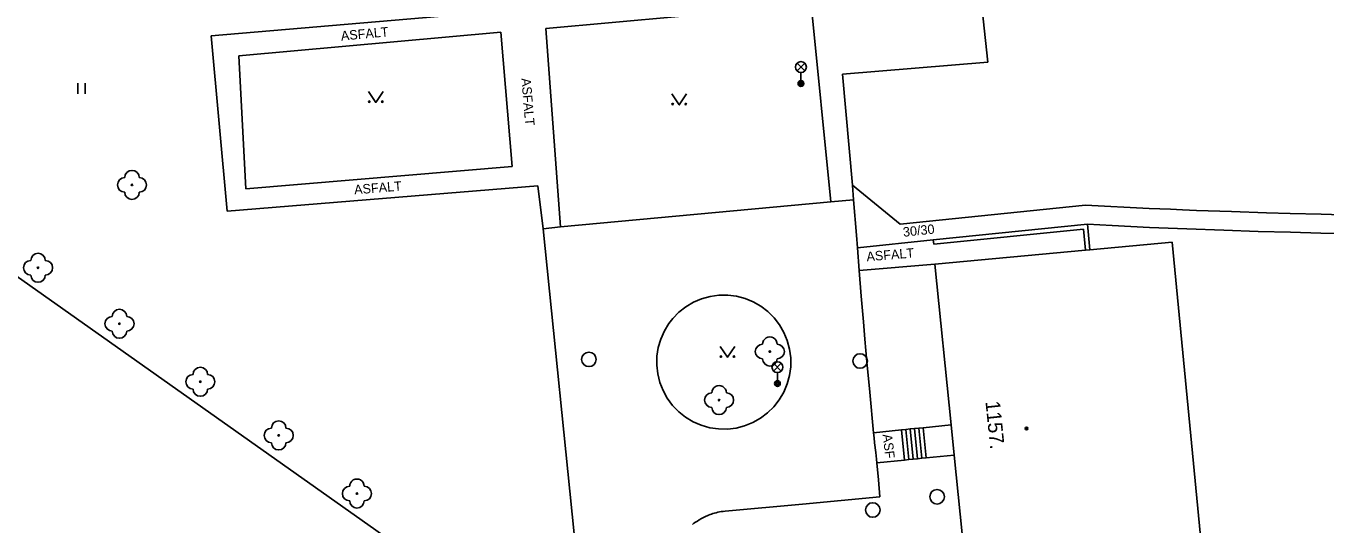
# Model space of a CAD drawing. Extents: x -539515 to -538098, y -1182060 to -1180157.
# Drawn here: x -538716.8 to -538627.4, y -1181091.3 to -1181057.1 of the extents above; entities that cross this region are included whole.
import ezdxf

# ---------------------------------------------------------------- set-up
doc = ezdxf.new("R2010")
doc.units = 0
for name, color, linetype in [('Vrstva 10', 7, 'Continuous'), ('Vrstva 11', 7, 'Continuous'), ('Vrstva 22', 7, 'Continuous'), ('Vrstva 27', 7, 'Continuous'), ('Vrstva 33', 7, 'Continuous'), ('Vrstva 36', 7, 'Continuous'), ('Vrstva 39', 7, 'Continuous'), ('Vrstva 40', 7, 'Continuous'), ('Vrstva 47', 7, 'Continuous'), ('Vrstva 5', 7, 'Continuous'), ('Vrstva 7', 7, 'Continuous')]:
    doc.layers.add(name, color=color, linetype=linetype)

msp = doc.modelspace()

# ---------------------------------------------------------------- linework, layer by layer
at = {"layer": 'Vrstva 10'}
for p, q in [((-538734.22, -1181062.4), (-538683.56, -1181098.18)), ((-538659.85, -1181069.02), (-538661.42, -1181069.16)), ((-538659.66, -1181071.445), (-538659.85, -1181069.02)), ((-538661.42, -1181069.16), (-538680, -1181070.87)), ((-538680, -1181070.87), (-538681.19, -1181071.01)), ((-538681.19, -1181071.01), (-538678.23, -1181100.27)), ((-538658.04, -1181089.45), (-538663.365, -1181089.94)), ((-538663.365, -1181089.94), (-538668.69, -1181090.43))]:
    msp.add_line(p, q, dxfattribs=at)
for points in [[(-538658.937, -1181080.161), (-538659.077, -1181078.589), (-538659.179, -1181077.409), (-538659.328, -1181075.64), (-538659.47, -1181073.87), (-538659.591, -1181072.326), (-538659.66, -1181071.445)], [(-538664.946, -1181077.612), (-538665.316, -1181077.131), (-538665.747, -1181076.702), (-538666.229, -1181076.334), (-538666.756, -1181076.033), (-538667.318, -1181075.803), (-538667.9, -1181075.65), (-538668.508, -1181075.573), (-538669.115, -1181075.578), (-538669.717, -1181075.662), (-538670.302, -1181075.824), (-538670.86, -1181076.062), (-538671.383, -1181076.371), (-538671.861, -1181076.746), (-538672.285, -1181077.18), (-538672.547, -1181077.517)], [(-538672.547, -1181077.517), (-538672.864, -1181078.035), (-538673.11, -1181078.59), (-538673.281, -1181079.173), (-538673.374, -1181079.773), (-538673.388, -1181080.38), (-538673.322, -1181080.983), (-538673.177, -1181081.573), (-538672.955, -1181082.138), (-538672.662, -1181082.67), (-538672.301, -1181083.158), (-538671.879, -1181083.595), (-538671.404, -1181083.972), (-538670.883, -1181084.284), (-538670.325, -1181084.525), (-538669.741, -1181084.69), (-538669.14, -1181084.777)], [(-538664.642, -1181078.138), (-538664.946, -1181077.612)], [(-538669.14, -1181084.777), (-538668.533, -1181084.785), (-538667.93, -1181084.713), (-538667.342, -1181084.562), (-538666.779, -1181084.335), (-538666.25, -1181084.037), (-538665.765, -1181083.671), (-538665.333, -1181083.245), (-538664.96, -1181082.766), (-538664.653, -1181082.242), (-538664.418, -1181081.682), (-538664.258, -1181081.096), (-538664.177, -1181080.495), (-538664.175, -1181079.887), (-538664.253, -1181079.285), (-538664.41, -1181078.699), (-538664.642, -1181078.138)], [(-538658.04, -1181089.45), (-538658.145, -1181088.28), (-538658.25, -1181087.11), (-538658.275, -1181086.852), (-538658.325, -1181086.401), (-538658.406, -1181085.726), (-538658.445, -1181085.388), (-538658.48, -1181085.05), (-538658.744, -1181082.256), (-538658.937, -1181080.161)], [(-538668.69, -1181090.43), (-538668.824, -1181090.445), (-538668.952, -1181090.463), (-538669.076, -1181090.486), (-538669.195, -1181090.511), (-538669.31, -1181090.539), (-538669.42, -1181090.569), (-538669.526, -1181090.601), (-538669.627, -1181090.635), (-538669.725, -1181090.671), (-538669.82, -1181090.708), (-538669.91, -1181090.745), (-538669.997, -1181090.784), (-538670.164, -1181090.864), (-538670.318, -1181090.945), (-538670.461, -1181091.026), (-538670.593, -1181091.108), (-538670.714, -1181091.187), (-538670.827, -1181091.266), (-538670.931, -1181091.342)]]:
    msp.add_lwpolyline(points, dxfattribs=at)
at = {"layer": 'Vrstva 11'}
for p, q in [((-538651.65, -1181049.65), (-538650.63, -1181059.54)), ((-538704.02, -1181057.74), (-538672.8, -1181055.06)), ((-538662.76, -1181055.59), (-538681.02, -1181057.24)), ((-538661.42, -1181069.16), (-538662.76, -1181055.59)), ((-538684.1, -1181057.49), (-538702.12, -1181059.12)), ((-538683.33, -1181066.73), (-538684.1, -1181057.49)), ((-538681.02, -1181057.24), (-538680, -1181070.87)), ((-538702.92, -1181069.8), (-538704.02, -1181057.74)), ((-538702.12, -1181059.12), (-538701.65, -1181068.25)), ((-538650.63, -1181059.54), (-538660.62, -1181060.37)), ((-538660.62, -1181060.37), (-538659.93, -1181068)), ((-538701.65, -1181068.25), (-538683.33, -1181066.73)), ((-538681.56, -1181068.05), (-538702.92, -1181069.8)), ((-538681.19, -1181071.01), (-538681.56, -1181068.05)), ((-538659.93, -1181068), (-538659.85, -1181069.02)), ((-538656.64, -1181070.68), (-538659.93, -1181068)), ((-538643.901, -1181069.386), (-538656.64, -1181070.68)), ((-538639.525, -1181069.601), (-538643.901, -1181069.386)), ((-538654.37, -1181071.77), (-538659.591, -1181072.326)), ((-538654.26, -1181073.44), (-538659.47, -1181073.87)), ((-538656.56, -1181084.84), (-538658.48, -1181085.05)), ((-538656.349, -1181086.917), (-538656.56, -1181084.84)), ((-538656.05, -1181086.886), (-538656.261, -1181084.809)), ((-538655.752, -1181086.856), (-538655.963, -1181084.779)), ((-538655.453, -1181086.826), (-538655.664, -1181084.749)), ((-538655.155, -1181086.795), (-538655.366, -1181084.718)), ((-538654.856, -1181086.765), (-538655.067, -1181084.688)), ((-538656.349, -1181086.917), (-538658.25, -1181087.11))]:
    msp.add_line(p, q, dxfattribs=at)
for points in [[(-538637.233, -1181069.704), (-538638.067, -1181069.668), (-538639.525, -1181069.601)], [(-538627.697, -1181070.009), (-538629.843, -1181069.948), (-538631.453, -1181069.9), (-538633.866, -1181069.823), (-538636.28, -1181069.74), (-538637.233, -1181069.704)], [(-538618.84, -1181070.228), (-538621.02, -1181070.178), (-538624.836, -1181070.085), (-538627.697, -1181070.009)], [(-538643.779, -1181070.694), (-538642.067, -1181070.779), (-538639.499, -1181070.909), (-538638.215, -1181070.969), (-538637.572, -1181070.996), (-538636.93, -1181071.02), (-538634.402, -1181071.107)], [(-538634.402, -1181071.107), (-538632.031, -1181071.183), (-538629.808, -1181071.249), (-538627.724, -1181071.307), (-538625.771, -1181071.359)], [(-538653.137, -1181084.492), (-538655.067, -1181084.688), (-538655.366, -1181084.718), (-538655.664, -1181084.749), (-538655.963, -1181084.779), (-538656.261, -1181084.809), (-538656.56, -1181084.84)], [(-538652.926, -1181086.569), (-538654.856, -1181086.765), (-538655.155, -1181086.795), (-538655.453, -1181086.826), (-538655.752, -1181086.856), (-538656.05, -1181086.886), (-538656.349, -1181086.917)]]:
    msp.add_lwpolyline(points, dxfattribs=at)
at = {"layer": 'Vrstva 22'}
for centre in [(-538709.47, -1181067.99), (-538715.93, -1181073.69), (-538710.33, -1181077.54), (-538665.61, -1181079.45), (-538704.77, -1181081.53), (-538669.1, -1181082.79), (-538699.38, -1181085.22), (-538694, -1181089.22)]:
    msp.add_circle(centre, 0.05, dxfattribs=at)
for centre, start, end in [((-538709.47, -1181067.49), 0, 180), ((-538709.97, -1181067.99), 90, 270), ((-538708.97, -1181067.99), 270, 90), ((-538709.47, -1181068.49), 180, 0), ((-538715.93, -1181073.19), 0, 180), ((-538716.43, -1181073.69), 90, 270), ((-538715.43, -1181073.69), 270, 90), ((-538715.93, -1181074.19), 180, 0), ((-538710.83, -1181077.54), 90, 270), ((-538710.33, -1181077.04), 0, 180), ((-538709.83, -1181077.54), 270, 90), ((-538710.33, -1181078.04), 180, 0), ((-538666.11, -1181079.45), 89.99978, 269.99978), ((-538665.61, -1181078.95), 359.99978, 179.99978), ((-538665.11, -1181079.45), 269.99978, 89.99978), ((-538704.77, -1181081.03), 0, 180), ((-538665.61, -1181079.95), 179.99978, 359.99977), ((-538705.27, -1181081.53), 90, 270), ((-538704.27, -1181081.53), 270, 90), ((-538704.77, -1181082.03), 180, 0), ((-538669.6, -1181082.79), 89.99978, 269.99978), ((-538669.1, -1181082.29), 359.99978, 179.99978), ((-538668.6, -1181082.79), 269.99978, 89.99978), ((-538669.1, -1181083.29), 179.99978, 359.99977), ((-538699.38, -1181084.72), 0, 180), ((-538699.88, -1181085.22), 90, 270), ((-538698.88, -1181085.22), 270, 90), ((-538699.38, -1181085.72), 180, 0), ((-538694.5, -1181089.22), 89.99978, 269.99978), ((-538694, -1181088.72), 359.99978, 179.99978), ((-538693.5, -1181089.22), 269.99978, 89.99978), ((-538694, -1181089.72), 179.99978, 359.99977)]:
    msp.add_arc(centre, 0.5, start, end, dxfattribs=at)
at = {"layer": 'Vrstva 27'}
for centre in [(-538678.05, -1181079.99), (-538659.4, -1181080.1), (-538654.11, -1181089.44), (-538658.53, -1181090.35)]:
    msp.add_circle(centre, 0.5, dxfattribs=at)
at = {"layer": 'Vrstva 33'}
for p, q in [((-538663.735, -1181060.15), (-538663.205, -1181059.62)), ((-538663.735, -1181059.62), (-538663.205, -1181060.15)), ((-538663.47, -1181060.26), (-538663.47, -1181061.01)), ((-538665.355, -1181080.79), (-538664.825, -1181080.26)), ((-538665.355, -1181080.26), (-538664.825, -1181080.79)), ((-538665.09, -1181080.9), (-538665.09, -1181081.65))]:
    msp.add_line(p, q, dxfattribs=at)
for centre, radius in [((-538663.47, -1181059.885), 0.375), ((-538663.47, -1181061.01), 0.2), ((-538663.47, -1181061.01), 0.145), ((-538663.47, -1181061.01), 0.0876), ((-538665.09, -1181080.525), 0.375), ((-538665.09, -1181081.65), 0.2), ((-538665.09, -1181081.65), 0.145), ((-538665.09, -1181081.65), 0.0876)]:
    msp.add_circle(centre, radius, dxfattribs=at)
at = {"layer": 'Vrstva 36'}
for p, q in [((-538713.2, -1181061.732), (-538713.2, -1181060.982)), ((-538712.7, -1181061.732), (-538712.7, -1181060.982))]:
    msp.add_line(p, q, dxfattribs=at)
for points in [[(-538693.207, -1181061.565), (-538692.707, -1181062.315), (-538692.207, -1181061.565)], [(-538672.342, -1181061.733), (-538671.842, -1181062.483), (-538671.342, -1181061.733)], [(-538669.025, -1181079.099), (-538668.525, -1181079.849), (-538668.025, -1181079.099)]]:
    msp.add_lwpolyline(points, dxfattribs=at)
for centre in [(-538693.157, -1181062.265), (-538692.258, -1181062.265), (-538672.292, -1181062.433), (-538671.393, -1181062.433), (-538668.975, -1181079.799), (-538668.076, -1181079.799)]:
    msp.add_circle(centre, 0.05, dxfattribs=at)
at = {"layer": 'Vrstva 39'}
for radius in [0.09, 0.0398]:
    msp.add_circle((-538647.957, -1181084.749), radius, dxfattribs=at)
at = {"layer": 'Vrstva 5'}
for p, q in [((-538643.913, -1181072.476), (-538654.26, -1181073.44)), ((-538643.615, -1181072.449), (-538643.913, -1181072.476)), ((-538637.94, -1181071.92), (-538643.615, -1181072.449)), ((-538637.94, -1181071.92), (-538635.83, -1181093.8)), ((-538654.26, -1181073.44), (-538653.137, -1181084.492)), ((-538653.137, -1181084.492), (-538652.926, -1181086.569)), ((-538652.926, -1181086.569), (-538652.024, -1181095.444))]:
    msp.add_line(p, q, dxfattribs=at)
at = {"layer": 'Vrstva 7'}
for p, q in [((-538643.779, -1181070.694), (-538643.615, -1181072.449)), ((-538654.339, -1181072.068), (-538644.048, -1181071.023)), ((-538644.048, -1181071.023), (-538643.913, -1181072.476))]:
    msp.add_line(p, q, dxfattribs=at)
for points in [[(-538643.779, -1181070.694), (-538654.37, -1181071.77)], [(-538654.37, -1181071.77), (-538654.339, -1181072.068)]]:
    msp.add_lwpolyline(points, dxfattribs=at)

# ---------------------------------------------------------------- texts
at = {"layer": 'Vrstva 40'}
for s, rotation, p in [('ASFALT', 5.16862, (-538695.078, -1181058.064)), ('ASFALT', 274.76364, (-538682.699, -1181060.667)), ('ASFALT', 4.68371, (-538694.169, -1181068.644)), ('30/30', 5.79927, (-538656.423, -1181071.557)), ('ASFALT', 4.71813, (-538658.941, -1181073.25)), ('ASF', 276.89874, (-538657.859, -1181085.164))]:
    msp.add_text(s, height=0.65, rotation=rotation, dxfattribs=at).set_placement(p)
at = {"layer": 'Vrstva 47'}
msp.add_text('1157.', height=1, rotation=275.80236, dxfattribs=at).set_placement((-538650.787, -1181082.889))

doc.saveas('drawing.dxf')
